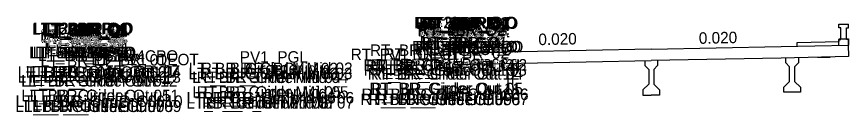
# Model space of a CAD drawing. Extents: x -26 to 3903, y -10 to 9531.
# Drawn here: x 1067 to 1175.8, y 1023.9 to 1036.8 of the extents above; entities that cross this region are included whole.
import ezdxf

# ---------------------------------------------------------------- set-up
doc = ezdxf.new("R2010")
doc.units = 0
for name, color, linetype in [('Prop CMT Conc Surface', 7, 'Continuous'), ('Prop XS Conc Monolithic Island', 7, 'Continuous'), ('Prop XS Finish Grade', 7, 'Continuous'), ('Prop XS SE Text', 7, 'Continuous')]:
    doc.layers.add(name, color=color, linetype=linetype)

msp = doc.modelspace()

# ---------------------------------------------------------------- linework, layer by layer
at = {"layer": 'Prop XS Conc Monolithic Island'}
for p, q in [((1174.53, 1035.34), (1174.53, 1035.84)), ((1174.53, 1035.84), (1175.78, 1035.84)), ((1175.78, 1035.34), (1175.78, 1035.84)), ((1124.22, 1034.31), (1124.22, 1034.81)), ((1124.22, 1034.81), (1125.47, 1034.81)), ((1125.47, 1034.31), (1125.47, 1034.81)), ((1174.78, 1035.34), (1174.53, 1035.34)), ((1174.78, 1033.84), (1174.78, 1035.34)), ((1175.53, 1033.84), (1175.53, 1035.34)), ((1175.53, 1035.34), (1175.78, 1035.34)), ((1124.47, 1034.31), (1124.22, 1034.31)), ((1124.47, 1032.81), (1124.47, 1034.31)), ((1125.22, 1032.81), (1125.22, 1034.31)), ((1125.22, 1034.31), (1125.47, 1034.31)), ((1174.53, 1033.08), (1174.53, 1033.84)), ((1174.53, 1033.84), (1174.78, 1033.84)), ((1175.78, 1033.84), (1175.53, 1033.84)), ((1175.78, 1033.08), (1175.78, 1033.84)), ((1124.22, 1032.05), (1124.22, 1032.81)), ((1124.22, 1032.81), (1124.47, 1032.81)), ((1125.47, 1032.81), (1125.22, 1032.81)), ((1125.47, 1032.05), (1125.47, 1032.81))]:
    msp.add_line(p, q, dxfattribs=at)
for points in [[(1150, 1032.56), (1133, 1032.22), (1124.22, 1032.05)], [(1126.29, 1032.09), (1131, 1032.18)], [(1150, 1032.56), (1167, 1032.9), (1175.78, 1033.08)], [(1175.75, 1033.11), (1175.78, 1031.58)], [(1124.22, 1032.05), (1124.25, 1030.55)], [(1175.78, 1031.58), (1167, 1031.4), (1150, 1031.06)], [(1150.83, 1031.08), (1150.83, 1030.4)], [(1167.59, 1030.76), (1167.59, 1031.41)], [(1169.26, 1031.45), (1169.26, 1030.76)], [(1171.75, 1031.5), (1172.58, 1031.51), (1173.42, 1031.53)], [(1124.25, 1030.55), (1133, 1030.72), (1150, 1031.06)], [(1128.25, 1030.63), (1127.42, 1030.61), (1126.58, 1030.59)], [(1130.74, 1030.68), (1130.74, 1030.03)], [(1130.74, 1030.03), (1131.24, 1029.53)], [(1131.91, 1029.53), (1132.41, 1030.03)], [(1132.41, 1030.03), (1132.41, 1030.71)], [(1149.17, 1031.05), (1149.17, 1030.4)], [(1149.17, 1030.4), (1149.67, 1029.9)], [(1150.83, 1030.4), (1150.33, 1029.9)], [(1168.09, 1030.26), (1167.59, 1030.76)], [(1168.09, 1028.35), (1168.09, 1030.26)], [(1169.26, 1030.76), (1168.76, 1030.26)], [(1168.76, 1030.26), (1168.76, 1028.35)], [(1131.24, 1029.53), (1131.24, 1027.61)], [(1131.91, 1027.61), (1131.91, 1029.53)], [(1149.67, 1029.9), (1149.67, 1027.98)], [(1150.33, 1029.9), (1150.33, 1027.98)], [(1149.67, 1027.98), (1148.92, 1027.23)], [(1150.33, 1027.98), (1151.08, 1027.23)], [(1167.34, 1027.6), (1168.09, 1028.35)], [(1168.76, 1028.35), (1169.51, 1027.6)], [(1131.24, 1027.61), (1130.49, 1026.86)], [(1130.49, 1026.86), (1130.49, 1026.19)], [(1132.66, 1026.86), (1131.91, 1027.61)], [(1132.66, 1026.19), (1132.66, 1026.86)], [(1148.92, 1027.23), (1148.92, 1026.56)], [(1151.08, 1027.23), (1151.08, 1026.56)], [(1167.34, 1026.93), (1167.34, 1027.6)], [(1169.51, 1026.93), (1168.42, 1026.93), (1167.34, 1026.93)], [(1169.51, 1027.6), (1169.51, 1026.93)], [(1130.49, 1026.19), (1131.58, 1026.19), (1132.66, 1026.19)], [(1148.92, 1026.56), (1150, 1026.56)], [(1151.08, 1026.56), (1150, 1026.56)]]:
    msp.add_lwpolyline(points, dxfattribs=at)
at = {"layer": 'Prop XS Finish Grade'}
for p, q in [((1169.07, 1032.94), (1169.07, 1033.44)), ((1130.93, 1032.18), (1130.93, 1032.74))]:
    msp.add_line(p, q, dxfattribs=at)
for points in [[(1169.07, 1032.94), (1169.07, 1033.44), (1174.57, 1033.55), (1174.57, 1033.9), (1175.78, 1033.9), (1175.78, 1033.08)], [(1130.93, 1032.18), (1130.93, 1032.74), (1125.43, 1032.79), (1125.43, 1033.14), (1124.22, 1033.14), (1124.22, 1032.05)]]:
    msp.add_lwpolyline(points, dxfattribs=at)

# ---------------------------------------------------------------- texts
at = {"layer": 'Prop CMT Conc Surface'}
for s, p in [('RT_2BMRP_O', (1119.01, 1035.28)), ('RT_3BMRP_O', (1119.15, 1035.28)), ('RT_5BMRP_O', (1119.24, 1035.2)), ('RT_4BR_O1', (1119.66, 1035.12)), ('RT_3BR_O1', (1119.74, 1035.22)), ('RT_2BR_O1', (1119.97, 1035.28)), ('RT_0BR_O1', (1120.05, 1035.12)), ('RT_5BR_O', (1120.06, 1035.01)), ('RT_1BR_O1', (1120.23, 1035.28)), ('LT_5BMRP_O', (1069.03, 1034.44)), ('LT_3BMRP_O', (1069.11, 1034.52)), ('LT_2BMRP_O', (1069.26, 1034.52)), ('LT_0BR_O1', (1070.31, 1034.36)), ('LT_2BR_O1', (1070.39, 1034.52)), ('LT_6BR_O1', (1070.39, 1034.19)), ('LT_1BR_O1', (1070.49, 1034.52)), ('LT_3BR_O1', (1070.62, 1034.46)), ('LT_7BR_O', (1070.63, 1034.19)), ('LT_4BR_O1', (1070.7, 1034.36)), ('LT_5BR_O', (1070.94, 1034.25)), ('RT_4BR_O2', (1119.44, 1034.28)), ('RT_3BR_O2', (1119.52, 1034.39)), ('RT_5BR_O2', (1119.52, 1034.18)), ('RT_2BR_O2', (1119.75, 1034.45)), ('RT_6BR_O2', (1119.75, 1034.12)), ('RT_0BR_O2', (1119.84, 1034.28)), ('RT_6BR_O1', (1119.97, 1034.95)), ('RT_1BR_O2', (1120.02, 1034.45)), ('RT_7BR_O1', (1120.05, 1034.12)), ('RT_7BR_O', (1120.38, 1034.95)), ('LT_0BR_O2', (1070.09, 1033.52)), ('LT_2BR_O2', (1070.17, 1033.69)), ('LT_6BR_O2', (1070.17, 1033.36)), ('LT_1BR_O2', (1070.27, 1033.69)), ('LT_7BR_O1', (1070.31, 1033.36)), ('LT_3BR_O2', (1070.4, 1033.63)), ('LT_5BR_O2', (1070.4, 1033.42)), ('LT_4BR_O2', (1070.49, 1033.52)), ('LT_2BR_O', (1070.96, 1032.86)), ('LT_3BR_O', (1071.05, 1032.87)), ('RT_3BR_O', (1119.96, 1033.63)), ('RT_2BR_O', (1120.05, 1033.62)), ('RT_0BR_O', (1120.38, 1033.13)), ('RT_6BR_O', (1120.38, 1032.88)), ('RT_1BR_O', (1120.56, 1033.38)), ('LT_0BR_O', (1070.63, 1032.37)), ('LT_6BR_O', (1070.63, 1032.12)), ('LT_5BR_O1', (1070.64, 1031.88)), ('LT_1BR_O', (1070.81, 1032.62)), ('LT_4BR_O', (1071.05, 1031.87)), ('RT_BR_2CPO', (1118.73, 1032.13)), ('RT_BR_3CPO', (1118.73, 1031.78)), ('RT_4BMRP_O', (1119.15, 1032.13)), ('RT_1BMRP_O', (1119.19, 1032.13)), ('RT_6BMRP_O', (1119.63, 1032.13)), ('RT_5BR_O1', (1119.73, 1032.64)), ('RT_4BR_O', (1119.96, 1032.63)), ('RT_BR_1CPO', (1120.12, 1032.13)), ('LT_6BMRP_O', (1068.63, 1031.37)), ('LT_BR_1CPO', (1068.79, 1031.37)), ('LT_4BMRP_O', (1069.11, 1031.37)), ('LT_1BMRP_O', (1069.44, 1031.37)), ('LT_BR_2CPO', (1069.82, 1031.37)), ('LT_BR_3CPO', (1069.82, 1031.02)), ('LT_BR_4CPO', (1075.32, 1030.91)), ('PV1_PGL', (1096.2, 1030.79)), ('RT_PV1_OEOT', (1110.71, 1031.13)), ('RT_BR_4CPO', (1113.23, 1031.67)), ('RT_BR_01', (1114.99, 1031.17)), ('RT_BR_02', (1121.48, 1031.31)), ('LT_BR_02', (1070.15, 1030.28)), ('LT_PV1_OEOT', (1076.8, 1030.45)), ('LT_BR_01', (1077.07, 1030.41)), ('RT_BR_Girder Out 14', (1112.38, 1029.73)), ('RT_BR_07', (1112.7, 1029.63)), ('RT_BR_Girder Out 01', (1113.3, 1029.74)), ('RT_BR_Girder Out 02', (1113.92, 1029.76)), ('RT_BR_06', (1121.43, 1029.81)), ('LT_BR_Girder Out 02', (1067.17, 1028.82)), ('LT_BR_Girder Out 01', (1068.22, 1028.84)), ('LT_BR_Girder Out 14', (1068.97, 1028.86)), ('LT_BR_06', (1070.11, 1028.78)), ('LT_BR_07', (1078.79, 1028.95)), ('LT_BR_Girder Mid 03', (1089.5, 1028.63)), ('LT_BR_Girder Mid 02', (1089.53, 1029.28)), ('RT_BR_Girder Mid 03', (1091.08, 1028.63)), ('RT_BR_Girder Mid 02', (1091.11, 1029.31)), ('BR_PGL', (1096.63, 1029.29)), ('RT_BR_Girder Out 13', (1112.4, 1029.08)), ('RT_BR_Girder Out 12', (1112.93, 1028.58)), ('RT_BR_Girder Out 04', (1113.37, 1028.58)), ('RT_BR_Girder Out 03', (1113.89, 1029.08)), ('LT_BR_Girder Out 03', (1067.15, 1028.17)), ('LT_BR_Girder Out 04', (1067.62, 1027.67)), ('LT_BR_Girder Out 12', (1068.52, 1027.67)), ('LT_BR_Girder Out 13', (1068.99, 1028.17)), ('LT_BR_Girder Mid 04', (1089.98, 1028.13)), ('RT_BR_Girder Mid 04', (1090.56, 1028.13)), ('RT_BR_Girder Out 11', (1113.15, 1026.66)), ('RT_BR_Girder Out 05', (1113.38, 1026.66)), ('LT_BR_Girder Out 05', (1067.64, 1025.76)), ('LT_BR_Girder Out 11', (1068.74, 1025.76)), ('LT_BR_Girder Mid 06', (1089.24, 1025.46)), ('LT_BR_Girder Mid 05', (1089.99, 1026.21)), ('RT_BR_Girder Mid 05', (1090.57, 1026.21)), ('RT_BR_Girder Mid 06', (1091.31, 1025.46)), ('RT_BR_Girder Out 09', (1111.96, 1025.24)), ('RT_BR_Girder Out 10', (1112.12, 1025.91)), ('RT_BR_Girder Out 08', (1113.04, 1025.24)), ('RT_BR_Girder Out 07', (1114.1, 1025.24)), ('RT_BR_Girder Out 06', (1114.12, 1025.91)), ('LT_BR_Girder Out 07', (1066.86, 1024.34)), ('LT_BR_Girder Out 06', (1066.88, 1025.01)), ('LT_BR_Girder Out 08', (1067.96, 1024.34)), ('LT_BR_Girder Out 09', (1069.05, 1024.34)), ('LT_BR_Girder Out 10', (1069.21, 1025.01)), ('LT_BR_Girder Mid 07', (1089.21, 1024.79)), ('RT_BR_Girder Mid 07', (1091.29, 1024.79)), ('BR_Girder Mid 08', (1091.77, 1024.79))]:
    msp.add_text(s, height=1.5, dxfattribs=at).set_placement(p)
at = {"layer": 'Prop XS SE Text'}
for p in [(1135.26, 1033.08), (1156.24, 1033.25)]:
    msp.add_text('0.020', height=1.5, rotation=1.1458, dxfattribs=at).set_placement(p)

doc.saveas('drawing.dxf')
